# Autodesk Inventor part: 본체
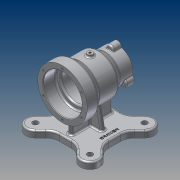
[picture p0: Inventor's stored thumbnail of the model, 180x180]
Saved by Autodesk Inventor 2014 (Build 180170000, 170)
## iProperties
Created: 2017-03
Part Number: 본체
Material: 알루미늄 6061
Document SubType Name: Modeling
Designer: Administrator
Mass: 1008.22 g
Surface Area: 841.711 cm^2
Volume: 372.037 cm^3
Density: 2.71 g/cm^3
Appearance: 알루미늄 - 평지
Author: Administrator
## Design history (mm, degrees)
sketch "스케치1"
  geometry: L1 (-50, 0)-(50, 0); L2 (-50, 36)-(-50, 45); L3 (-50, 45)-(-30, 45); L4 (-30, 45)-(-19, 36); L5 (-19, 36)-(15, 36); L6 (15, 36)-(27, 27.5); L7 (27, 27.5)-(50, 27.5); L8 (50, 27.5)-(50, 18.5); L9 (49, 17.5)-(23, 17.5); L10 (20, 20.5)-(20, 23); L11 (17, 26)-(-24, 26); L12 (-27, 29)-(-27, 32); L13 (-30, 35)-(-49, 35); L14 (-50, 36)-(-49, 35); L15 (49, 17.5)-(50, 18.5); L16 (-45, -70)-(45, -70); L17 (45, -70)-(45, -82); L18 (45, -82)-(-45, -82); L19 (-45, -82)-(-45, -70); A1 r 3 centre (-24, 29) between (-27, 29) and (-24, 26); A2 r 3 centre (23, 20.5) between (20, 20.5) and (23, 17.5); A3 r 3 centre (17, 23) between (20, 23) and (17, 26); A4 r 3 centre (-30, 32) between (-27, 32) and (-30, 35); 5 further points
  constraints: 38 end point, 8 point on circle, 8 tangent, 7 perpendicular, 6 parallel, 4 centre point, 4 point on line, 3 vertical alignment, 2 equal radius, 2 horizontal, 2 midpoint, 1 coincident
  dimensions: "d0" = 100 distance of L1.start L1.end; "d1" = 35 diameter of L9 L1; "d2" = 52 diameter of L11 L1; "d3" = 70 diameter of L13 L1; "d4" = 90 diameter of L3 L1; "d5" = 20 distance of L2.end L3.end; "d6" = 65 distance from line of L2 L5.end; "d7" = 23 distance of L6.end L7.end; "d8" = 31 distance from line of L2 L4.end; "d9" = 3 radius of A1; "d10" = 3 radius of A3; "d11" = 72 diameter of L5 L1; "d12" = 55 diameter of L7 L1; "d13" = 30 distance between parallel lines of L8 L10; "d14" = 23 distance from line of L2 L12.end; "d15" = 1 distance of L2.start point (-50, 35); "d16" = 1 distance of L13.end point (-50, 35) (= d15); "d17" = 1 distance of L9.start point (50, 17.5) (= d15); "d18" = 1 distance of L8.end point (50, 17.5) (= d17); "d19" = 82 distance from line of L18 L1.end; "d20" = 12 distance of L16.end L17.end; "d21" = 90 distance of L16.start L16.end
revolve "회전1" stored, may be unused: angle "d22" = 90 deg
extrude "돌출1" join sketch "스케치1" stored distance "d23" = 90; taper "d24" = 0 deg
sketch "스케치2"
  geometry: L1 (45, 45)-(94.497, 94.497); L2 (45, 45)-(115, 45); L3 (94.497, 94.497)-(45, 45); L4 (-4.497, -4.497)-(45, 45); L5 (45, 45)-(-4.497, 94.497); L6 (45, 45)-(94.497, -4.497); L7 (90, 0)-(90, 90) reference; L8 (0, 0)-(90, 0) reference; L9 (0, 0)-(0, 90) reference; L10 (90, 90)-(0, 90) reference; L11 (0, 65.958)-(-16.518, 82.477); L12 (24.042, 90)-(7.523, 106.518); L13 (0, 65.958)-(0, 90); L14 (0, 90)-(24.042, 90); L15 (45, 45)-(-66.566, 45); L16 (0, 24.042)-(-16.518, 7.523); L17 (24.042, 0)-(7.523, -16.518); L18 (0, 24.042)-(0, 0); L19 (0, 0)-(24.042, 0); C1 r 5 at (-4.497, 94.497); C2 r 5 at (-4.497, -4.497); A1 r 70 centre (45, 45) between (94.497, 94.497) and (-4.497, -4.497); A2 r 17 centre (-4.497, 94.497) between (7.523, 106.518) and (-16.518, 82.477); A3 r 17 centre (-4.497, -4.497) between (-16.518, 7.523) and (7.523, -16.518); 1 further point
  constraints: 30 end point, 8 point on circle, 6 symmetric about line, 5 centre point, 5 collinear, 4 coincident, 3 parallel, 3 perpendicular, 2 point on line, 1 equal length, 1 horizontal, 2 other
  dimensions: "d25" = 140 diameter of A1; "d26" = 45 deg angle of L2 L1; "d28" = 34 diameter of A2; "d31" = 17 distance between parallel lines of L12 L5; "d32" = 17 distance between parallel lines of L5 L11; "d33" = 10 diameter of C1
extrude "돌출2" join sketch "스케치2" distance "d34" = 12; taper "d35" = 0 deg
fillet "모깎기1" dims "d36" = 25
sketch "스케치3"
  geometry: L1 (47.603, 49)-(-26.397, 49); L2 (-26.397, 49)-(-26.397, 41); L3 (-26.397, 41)-(47.603, 41); L4 (47.603, 41)-(47.603, 49); L5 (47.603, 49)-(-26.397, 41); L6 (-26.397, 49)-(47.603, 41); 1 further point
  constraints: 12 end point, 2 midpoint, 2 parallel, 1 horizontal, 1 perpendicular
  dimensions: "d37" = 74 distance of L1.start L1.end; "d38" = 8 distance of L1.end L2.end
extrude "돌출3" join sketch "스케치3" stored distance "d39" = 12; taper "d40" = 0 deg
sketch "스케치4"
  geometry: L1 (-70, 10.603)-(-70, 28.281) reference; L2 (-70, 28.281)-(-70, 37.477) reference; L3 (-70, -28.281)-(-70, -10.603) reference; L4 (-70, -37.477)-(-70, -28.281) reference; L5 (-70, 25)-(-31.096, 18.14); A1 r 36 centre (0, 0) between (-35.777, -4) and (-35.777, 4) reference; 1 further point
  constraints: 2 end point, 1 point on circle, 1 point on line
  dimensions: "d41" = 25 vertical distance of point (0, 0) L5.start; "d42" = 100 deg angle of L2 L5
feature "리브1" sketch "스케치4" dims "d43" = 1, "d44" = 8, "d45" = 0, "d46" = 0, "d47" = 1, "d48" = 1
node "작업 평면1"
sketch "스케치5"
  geometry: C1 r 5 at (0, 0); 1 further point
  constraints: 1 centre point, 1 coincident
  dimensions: "d50" = 10 diameter of C1
extrude "돌출4" join sketch "스케치5" stored distance "d51" = 12; taper "d52" = 0 deg
hole "구멍1" diameter "d55" = 4.134; stored, may be unused: countersink angle "d59" = 90 deg, drill point angle "d61" = 118 deg; dims "d53" = 10, "d54" = 10, "d56" = 6, "d57" = 4, "d58" = 2, "d60" = 8
sketch "스케치6"
  geometry: A1 r 27.5 centre (0, 0) between (0, 27.5) and (-6.943, 26.609) reference; A2 r 7 centre (0, 27.5) between (6.943, 26.609) and (-6.943, 26.609); 1 further point
  constraints: 5 point on circle, 1 centre point, 1 vertical alignment
  dimensions: "d62" = 14 diameter of A2
extrude "돌출5" join sketch "스케치6" distance "d63" = 15; taper "d64" = 0 deg
sketch "스케치7"
  geometry: 2 further points
  constraints: 1 vertical alignment
  dimensions: "d65" = 27.5 distance of point (0, -27.5) point (0, 0)
hole "구멍2" sketch "스케치7" at (0, 0) diameter "d66" = 2.459; stored, may be unused: countersink angle "d70" = 90 deg, drill point angle "d72" = 118 deg; dims "d67" = 9, "d68" = 4, "d69" = 2, "d71" = 11
fillet "모깎기2" dims "d73" = 3
fillet "모깎기3" dims "d74" = 1
sketch "스케치8"
  geometry: 2 further points
  constraints: 1 vertical alignment, 1 other
  dimensions: "d78" = 35 distance of point (10.603, 10) point (10.603, 45)
feature "엠보싱1" sketch "스케치8" dims "d0" = 100, "d1" = 35, "d2" = 52, "d3" = 70, "d4" = 90, "d5" = 20, "d6" = 65, "d7" = 23, "d8" = 31, "d9" = 3, "d10" = 3, "d11" = 72, "d12" = 55, "d13" = 30, "d14" = 23, "d15" = 1, "d16" = 1 (= d15), "d17" = 1 (= d15), "d18" = 1 (= d17), "d19" = 82, "d20" = 12, "d21" = 90, "d79" = 0.5, "d80" = 0
fillet "모깎기4" dims "d81" = 3
fillet "모깎기5" dims "d82" = 3
fillet "모깎기6" dims "d83" = 3
sketch "스케치9"
  geometry: 2 further points
  constraints: 1 vertical alignment
  dimensions: "d84" = 40 distance of point (0, 0) point (0, 40)
hole "구멍3" sketch "스케치9" at (0, 40) diameter "d85" = 3.242; stored, may be unused: countersink angle "d89" = 90 deg, drill point angle "d91" = 118 deg; dims "d86" = 9, "d87" = 4, "d88" = 2, "d90" = 11
node "솔리드1"
mirror "대칭1"
mirror "대칭2"
pattern_circular "원형 패턴1" dims "d76" = 360 deg
pattern_circular "원형 패턴2" dims angle "d93" = 360 deg
node "투영된 루프1"
